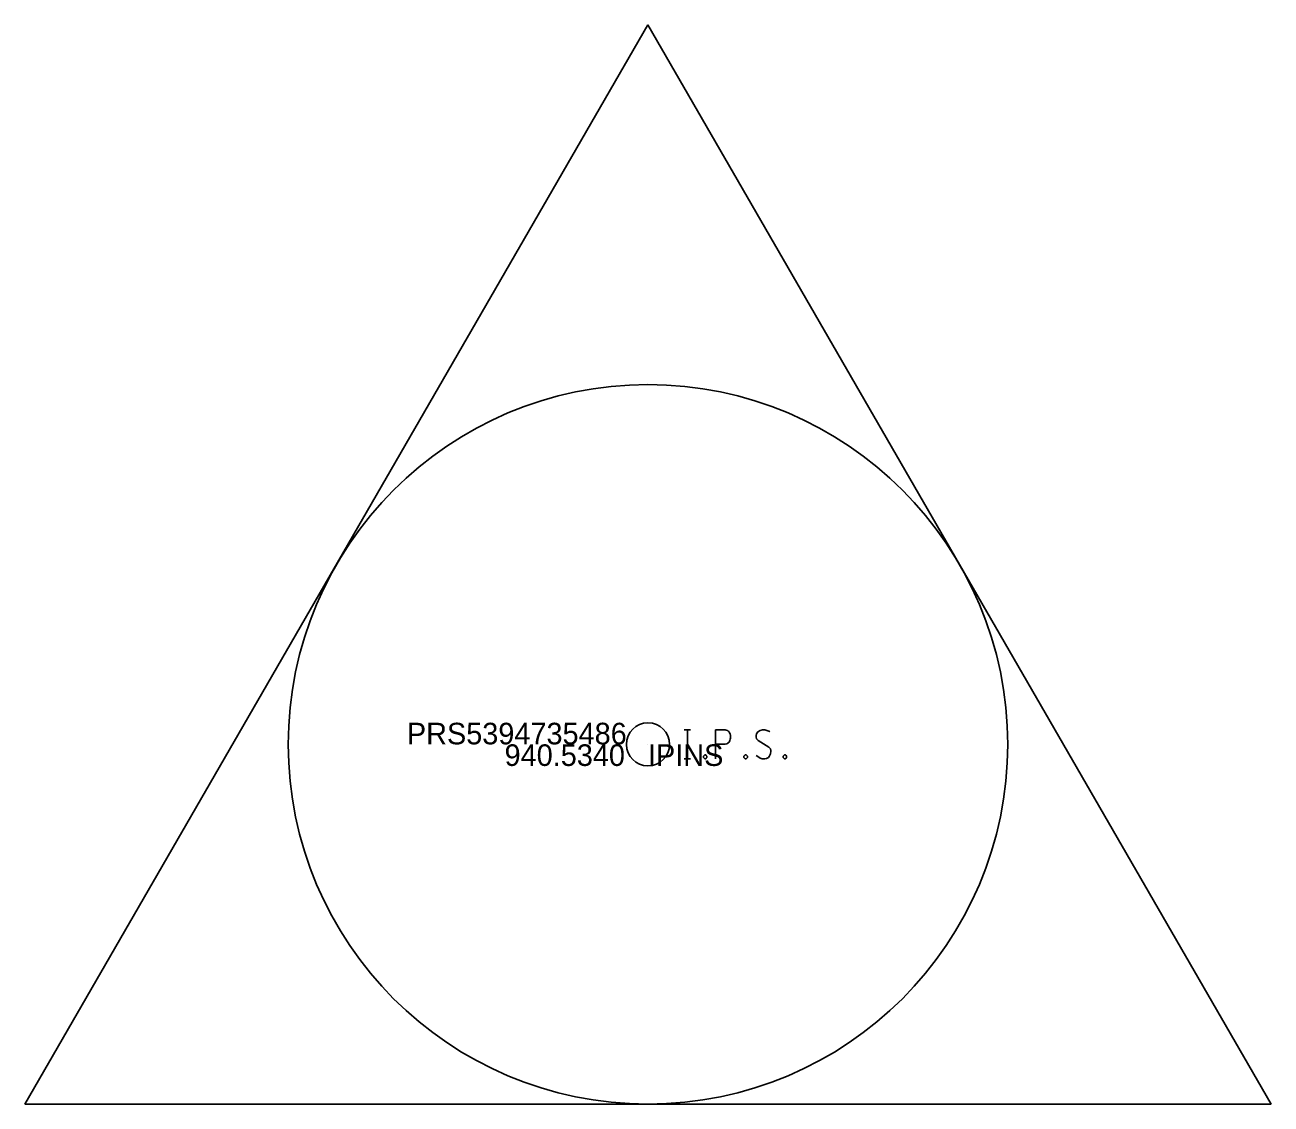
# Model space of a CAD drawing. Extents: x 1479481 to 1575806, y 316056 to 379927.
# Drawn here: x 1575802.822 to 1575806.286, y 316056.23 to 316059.23 of the extents above; entities that cross this region are included whole.
import ezdxf

# ---------------------------------------------------------------- set-up
doc = ezdxf.new("R2010")
doc.units = 0
for name, color, linetype in [('SV_Control_Point', 7, 'Continuous'), ('SV_P_Mon_Cells_Set', 7, 'Continuous'), ('SV_X_Text_Comment', 7, 'Continuous'), ('SV_X_Text_Elevation', 7, 'Continuous'), ('SV_X_Text_Name', 7, 'Continuous')]:
    doc.layers.add(name, color=color, linetype=linetype)

msp = doc.modelspace()

# ---------------------------------------------------------------- linework, layer by layer
at = {"layer": 'SV_Control_Point'}
for p, q in [((1575802.8219, 316056.23), (1575804.554, 316059.23)), ((1575804.554, 316059.23), (1575806.2861, 316056.23)), ((1575804.554, 316057.23), (1575804.554, 316057.23)), ((1575806.2861, 316056.23), (1575802.8219, 316056.23))]:
    msp.add_line(p, q, dxfattribs=at)
msp.add_circle((1575804.554, 316057.23), 1, dxfattribs=at)
at = {"layer": 'SV_P_Mon_Cells_Set'}
for points in [[(1575804.6549, 316057.2701), (1575804.6726, 316057.2701)], [(1575804.6638, 316057.1901), (1575804.6638, 316057.2701)], [(1575804.742, 316057.1901), (1575804.742, 316057.2701), (1575804.7685, 316057.2701), (1575804.7712, 316057.2695), (1575804.7751, 316057.2682), (1575804.7768, 316057.2669), (1575804.7784, 316057.2657), (1575804.7806, 316057.2625), (1575804.7823, 316057.2594), (1575804.7834, 316057.2543), (1575804.7834, 316057.2468), (1575804.7828, 316057.2443), (1575804.7817, 316057.2405), (1575804.7795, 316057.2361), (1575804.7773, 316057.2342), (1575804.7757, 316057.2329), (1575804.7729, 316057.2317), (1575804.7685, 316057.231), (1575804.742, 316057.231)], [(1575804.8925, 316057.2644), (1575804.8914, 316057.2657), (1575804.8897, 316057.2669), (1575804.8848, 316057.2688), (1575804.8787, 316057.2701), (1575804.8743, 316057.2701), (1575804.8727, 316057.2701), (1575804.8655, 316057.2682), (1575804.8594, 316057.2644), (1575804.8556, 316057.2594), (1575804.8545, 316057.2543), (1575804.8545, 316057.2506), (1575804.8556, 316057.2455), (1575804.86, 316057.2411), (1575804.8903, 316057.2222), (1575804.893, 316057.2197), (1575804.8941, 316057.2172), (1575804.8952, 316057.2134), (1575804.8952, 316057.2096), (1575804.8947, 316057.2058), (1575804.8941, 316057.2033), (1575804.893, 316057.2002), (1575804.8919, 316057.1977), (1575804.8908, 316057.1958), (1575804.8892, 316057.1939), (1575804.8875, 316057.1926), (1575804.8853, 316057.1914), (1575804.8837, 316057.1907), (1575804.8787, 316057.1901), (1575804.871, 316057.1901), (1575804.866, 316057.1914), (1575804.8589, 316057.1958), (1575804.8545, 316057.1995)], [(1575804.6549, 316057.1901), (1575804.6726, 316057.1901)], [(1575804.7117, 316057.2008), (1575804.7145, 316057.2008), (1575804.7161, 316057.1995), (1575804.7178, 316057.197), (1575804.7178, 316057.1939), (1575804.7161, 316057.1914), (1575804.7145, 316057.1901), (1575804.7117, 316057.1901), (1575804.7101, 316057.1914), (1575804.7084, 316057.1939), (1575804.7084, 316057.197), (1575804.7101, 316057.1995), (1575804.7117, 316057.2008)], [(1575804.8242, 316057.2008), (1575804.8269, 316057.2008), (1575804.8286, 316057.1995), (1575804.8302, 316057.197), (1575804.8302, 316057.1939), (1575804.8286, 316057.1914), (1575804.8269, 316057.1901), (1575804.8242, 316057.1901), (1575804.8225, 316057.1914), (1575804.8208, 316057.1939), (1575804.8208, 316057.197), (1575804.8225, 316057.1995), (1575804.8242, 316057.2008)], [(1575804.9333, 316057.2008), (1575804.936, 316057.2008), (1575804.9377, 316057.1995), (1575804.9393, 316057.197), (1575804.9393, 316057.1939), (1575804.9377, 316057.1914), (1575804.936, 316057.1901), (1575804.9333, 316057.1901), (1575804.9316, 316057.1914), (1575804.93, 316057.1939), (1575804.93, 316057.197), (1575804.9316, 316057.1995), (1575804.9333, 316057.2008)]]:
    msp.add_lwpolyline(points, dxfattribs=at)
msp.add_circle((1575804.554, 316057.23), 0.06, dxfattribs=at)

# ---------------------------------------------------------------- texts
at = {"layer": 'SV_X_Text_Comment'}
msp.add_text('IPINS', height=0.06, dxfattribs=at).set_placement((1575804.554, 316057.17))
at = {"layer": 'SV_X_Text_Elevation'}
msp.add_text('940.5340', height=0.06, dxfattribs=at).set_placement((1575804.1553, 316057.17))
at = {"layer": 'SV_X_Text_Name'}
msp.add_text('PRS5394735486', height=0.06, dxfattribs=at).set_placement((1575803.8837, 316057.23))

doc.saveas('drawing.dxf')
